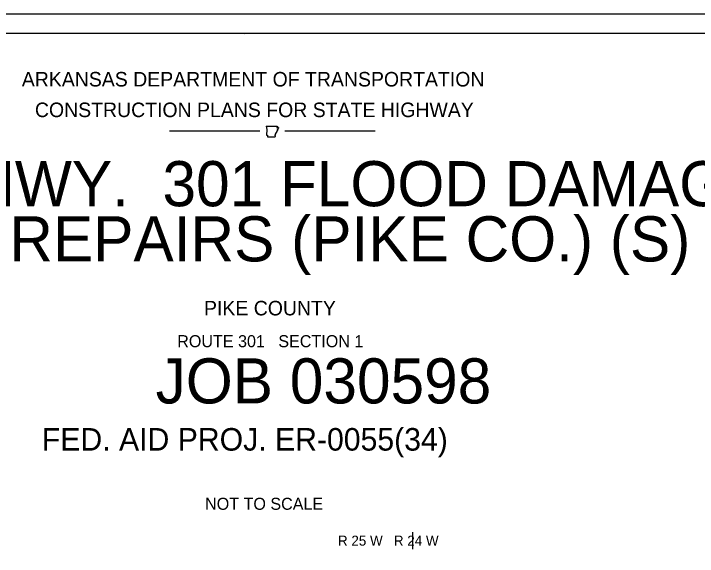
# Model space of a CAD drawing. Extents: x 79818 to 83933, y 50884 to 53307.
# Drawn here: x 81790 to 83152, y 52225 to 53307 of the extents above; entities that cross this region are included whole.
import ezdxf

# ---------------------------------------------------------------- set-up
doc = ezdxf.new("R2010")
doc.units = 0
for name, color, linetype in [('Default', 7, 'Continuous'), ('R_Border', 7, 'Continuous'), ('R_Draft', 7, 'Continuous'), ('R_No Plot', 7, 'Continuous')]:
    doc.layers.add(name, color=color, linetype=linetype)

msp = doc.modelspace()

# ---------------------------------------------------------------- linework, layer by layer
at = {"layer": 'Default'}
for p, q in [((82100.40710546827, 53073.55544833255), (82280.40674546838, 53073.55544833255)), ((82330.40664546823, 53073.55544833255), (82510.40628546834, 53073.55544833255)), ((82585.0374669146, 52239.6791267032), (82585.0374669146, 52273.6791267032))]:
    msp.add_line(p, q, dxfattribs=at)
for points in [[(82293.18594448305, 53083.023599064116), (82299.65393154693, 53083.0195990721), (82305.3299201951, 53083.03159904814), (82312.02590680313, 53083.13559884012), (82315.12990059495, 53083.20759869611)], [(82293.18594448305, 53083.023599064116), (82294.01394282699, 53076.37561236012), (82293.65394354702, 53065.52363406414)], [(82314.16990251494, 53080.08360494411), (82317.20589644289, 53080.23960463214)], [(82295.86593912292, 53064.87963535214), (82295.87393910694, 53061.64364182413), (82310.53390978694, 53061.61964187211)]]:
    msp.add_lwpolyline(points, dxfattribs=at)
for points in [[(82315.12990059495, 53083.20759869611), (82315.14990055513, 53083.03159904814), (82315.20590044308, 53082.93959923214), (82315.2139004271, 53082.77159956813), (82315.28190029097, 53082.699599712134), (82315.39790005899, 53082.62759985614), (82315.50189985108, 53082.51160008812), (82315.52589980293, 53082.37560036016), (82315.49389986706, 53082.23560064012), (82315.48589988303, 53082.07960095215), (82315.46989991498, 53081.94360122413), (82315.4458999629, 53081.81960147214), (82315.34990015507, 53081.719601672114), (82315.25790033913, 53081.64760181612), (82315.17390050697, 53081.56360198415), (82315.1139006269, 53081.4756021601), (82315.00990083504, 53081.37960235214), (82314.90590104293, 53081.27960255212), (82314.82190121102, 53081.19160272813), (82314.7379013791, 53081.07960295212), (82314.69790145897, 53080.95560320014), (82314.60590164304, 53080.86760337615), (82314.53390178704, 53080.78760353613), (82314.43790197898, 53080.679603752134), (82314.38990207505, 53080.57160396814), (82314.29790225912, 53080.4476042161), (82314.27790229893, 53080.32760445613), (82314.2179024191, 53080.231604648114), (82314.21390242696, 53080.215604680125)], [(82317.1618965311, 53080.235604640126), (82317.20589644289, 53080.23960463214), (82317.3418961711, 53080.09560492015), (82317.40189605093, 53079.97560516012), (82317.48989587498, 53079.90760529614), (82317.58989567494, 53079.87160536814), (82317.66589552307, 53079.77960555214), (82317.71789541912, 53079.67960575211), (82317.68989547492, 53079.59160592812), (82317.57789569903, 53079.58360594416), (82317.45389594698, 53079.56360598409), (82317.33389618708, 53079.5676059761), (82317.237896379, 53079.48760613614), (82317.32589620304, 53079.37960635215), (82317.44189597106, 53079.279606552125), (82317.47389590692, 53079.171606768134), (82317.40989603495, 53079.067606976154), (82317.28189629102, 53079.01160708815), (82317.15789653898, 53078.963607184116), (82317.04589676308, 53078.8676073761), (82316.99389686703, 53078.77560756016), (82316.869897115, 53078.73560764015), (82316.74189737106, 53078.69960771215), (82316.62989759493, 53078.68760773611), (82316.50189785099, 53078.663607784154), (82316.37789809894, 53078.60360790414), (82316.3258982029, 53078.4996081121), (82316.34189817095, 53078.35160840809), (82316.33789817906, 53078.195608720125), (82316.46989791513, 53078.14360882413), (82316.5858976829, 53078.13960883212), (82316.69789745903, 53078.0796089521), (82316.68589748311, 53077.99160912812), (82316.60189765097, 53077.879609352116), (82316.50189785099, 53077.791609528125), (82316.40189805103, 53077.747609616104), (82316.30989823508, 53077.663609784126), (82316.34189817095, 53077.579609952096), (82316.4258980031, 53077.52361006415), (82316.48589788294, 53077.431610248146), (82316.47789789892, 53077.34761041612), (82316.38189809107, 53077.2876105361), (82316.27789829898, 53077.31161048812), (82316.2018984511, 53077.411610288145), (82316.11389862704, 53077.44361022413), (82316.03789877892, 53077.47961015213), (82315.9498989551, 53077.427610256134), (82315.9498989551, 53077.31161048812), (82315.917899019, 53077.18761073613), (82315.94589896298, 53077.09561092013), (82315.98189889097, 53076.96761117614), (82315.97789889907, 53076.87161136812), (82315.94589896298, 53076.7356116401), (82315.87789909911, 53076.59561192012), (82315.7978992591, 53076.551612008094), (82315.76589932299, 53076.70361170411), (82315.74989935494, 53076.82761145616), (82315.70189945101, 53076.899611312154), (82315.63789957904, 53076.90361130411), (82315.5538997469, 53076.84361142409), (82315.46189993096, 53076.751611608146), (82315.34590016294, 53076.65161180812), (82315.27790029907, 53076.551612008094), (82315.31390022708, 53076.42761225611), (82315.40190005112, 53076.39561232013), (82315.46989991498, 53076.41961227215), (82315.50589984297, 53076.49961211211), (82315.57389970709, 53076.51161208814), (82315.63789957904, 53076.38761233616)], [(82311.1459085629, 53067.13163084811), (82311.105908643, 53067.03963103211), (82311.06190873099, 53066.87963135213), (82311.07390870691, 53066.7436316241), (82311.13390858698, 53066.62763185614), (82311.22990839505, 53066.563631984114), (82311.33390818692, 53066.47163216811), (82311.32590820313, 53066.331632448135), (82311.26590832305, 53066.27963255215), (82311.12590860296, 53066.315632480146), (82311.01790881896, 53066.36363238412), (82310.92590900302, 53066.335632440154), (82310.80190925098, 53066.27563256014), (82310.70990943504, 53066.263632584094), (82310.71390942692, 53066.07163296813), (82310.83790917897, 53065.93563324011), (82310.94590896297, 53065.93563324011), (82311.06990871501, 53065.91963327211), (82311.11390862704, 53065.77563356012), (82311.04190877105, 53065.65563380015), (82310.92190901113, 53065.59563392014), (82310.76990931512, 53065.66763377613), (82310.66190953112, 53065.74363362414), (82310.55390974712, 53065.81563348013), (82310.41791001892, 53065.85163340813), (82310.34191017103, 53065.83563344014), (82310.30591024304, 53065.66763377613), (82310.36991011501, 53065.51563408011), (82310.4739099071, 53065.41163428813), (82310.56990971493, 53065.27563456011), (82310.55390974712, 53065.17563476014), (82310.48190989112, 53065.14763481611), (82310.35391014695, 53065.11963487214), (82310.27791029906, 53065.079634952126), (82310.25791033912, 53065.04763501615), (82310.297910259, 53064.91163528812), (82310.33391018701, 53064.76363558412), (82310.33391018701, 53064.65163580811), (82310.28991027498, 53064.547636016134), (82310.22191041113, 53064.38763633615), (82310.2299103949, 53064.28363654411), (82310.27791029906, 53064.23563664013), (82310.3379101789, 53064.251636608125), (82310.41791001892, 53064.30763649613), (82310.46990991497, 53064.371636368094), (82310.513909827, 53064.45163620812), (82310.59790965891, 53064.51963607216), (82310.701909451, 53064.45963619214), (82310.72590940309, 53064.3356364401), (82310.66590952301, 53064.227636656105), (82310.5819096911, 53064.17963675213), (82310.477909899, 53064.13963683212), (82310.4019100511, 53064.05163700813), (82310.42191001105, 53063.94763721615), (82310.48190989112, 53063.891637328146), (82310.62990959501, 53063.91963727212), (82310.72990939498, 53063.96363718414), (82310.78590928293, 53064.019637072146), (82310.85390914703, 53064.08763693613), (82310.88990907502, 53064.15563680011), (82310.94190897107, 53064.227636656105), (82311.03390878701, 53064.24763661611), (82311.07790869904, 53064.187636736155), (82311.06190873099, 53064.05163700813), (82311.00590884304, 53063.92363726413), (82310.92990899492, 53063.81563748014), (82310.845909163, 53063.739637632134), (82310.7419093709, 53063.57563796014), (82310.76190933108, 53063.42363826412), (82310.80190925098, 53063.29963851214), (82310.85790913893, 53063.20363870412), (82310.95390894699, 53063.22363866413), (82311.06190873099, 53063.23563864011), (82311.12590860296, 53063.183638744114), (82311.11790861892, 53063.07163896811), (82311.0379087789, 53062.96363918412), (82310.96190893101, 53062.85963939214), (82310.92190901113, 53062.71563968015), (82310.93790897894, 53062.615639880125), (82310.93790897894, 53062.52364006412), (82310.90590904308, 53062.423640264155), (82310.84990915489, 53062.36764037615), (82310.701909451, 53062.3716403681), (82310.5459097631, 53062.3876403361), (82310.46190993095, 53062.33964043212), (82310.477909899, 53062.20364070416), (82310.56990971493, 53062.103640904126), (82310.6339095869, 53062.05164100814), (82310.72590940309, 53061.93964123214), (82310.76590932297, 53061.847641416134), (82310.75390934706, 53061.76764157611), (82310.69790945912, 53061.69964171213), (82310.53390978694, 53061.61964187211)], [(82313.90190305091, 53072.42362026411), (82313.80990323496, 53072.307620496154), (82313.67390350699, 53072.37962035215), (82313.67390350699, 53072.475620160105), (82313.69390346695, 53072.57561996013), (82313.64590356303, 53072.6396198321), (82313.56190373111, 53072.61161988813), (82313.56190373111, 53072.48762013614), (82313.55390374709, 53072.36762037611), (82313.529903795, 53072.19562072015), (82313.58590368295, 53072.1436208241), (82313.71390342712, 53072.12762085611), (82313.80590324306, 53072.10362090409), (82313.86190313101, 53072.011621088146), (82313.85790313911, 53071.89962131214), (82313.8139032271, 53071.79162152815), (82313.74990335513, 53071.7036217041), (82313.64990355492, 53071.67162176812), (82313.56990371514, 53071.72362166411), (82313.53790377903, 53071.82762145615), (82313.50190385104, 53071.91962127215), (82313.43390398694, 53071.98762113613), (82313.36190413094, 53071.91162128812), (82313.34590416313, 53071.77162156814), (82313.34990415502, 53071.651621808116), (82313.34990415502, 53071.48762213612), (82313.45390394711, 53071.37962235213), (82313.51790381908, 53071.25562260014), (82313.49790385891, 53071.14362282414), (82313.42190401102, 53071.011623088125), (82313.38990407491, 53070.8956233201), (82313.35790413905, 53070.73962363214), (82313.36190413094, 53070.567623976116), (82313.33390418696, 53070.39962431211), (82313.27790429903, 53070.2876245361), (82313.17390450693, 53070.195624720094), (82313.10590464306, 53070.13562484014), (82313.04990475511, 53070.075624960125), (82313.02190481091, 53069.95562520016), (82313.00190485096, 53069.87162536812), (82312.92590500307, 53069.77162556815), (82312.86590512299, 53069.76362558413), (82312.81790521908, 53069.80362550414), (82312.80190525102, 53069.87162536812), (82312.80190525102, 53069.9396252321), (82312.76990531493, 53070.00762509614), (82312.66990551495, 53070.03562504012), (82312.58990567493, 53070.031625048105), (82312.55390574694, 53069.9756251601), (82312.605905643, 53069.819625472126), (82312.62590560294, 53069.7196256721), (82312.59790565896, 53069.58362594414), (82312.61390562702, 53069.567625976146), (82312.46990591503, 53069.49162612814), (82312.35390614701, 53069.4796261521), (82312.25790633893, 53069.45162620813), (82312.16590652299, 53069.39162632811), (82312.12190661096, 53069.30362650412), (82312.05790673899, 53069.23162664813), (82312.00190685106, 53069.163626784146), (82311.92590700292, 53069.1316268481), (82311.84190717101, 53069.14762681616), (82311.72990739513, 53069.159626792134), (82311.66590752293, 53069.079626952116), (82311.6859074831, 53068.96362718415), (82311.76190733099, 53068.89562732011), (82311.87390710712, 53068.863627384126), (82311.98990687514, 53068.87162736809), (82312.10190665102, 53068.883627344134), (82312.20590644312, 53068.82762745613), (82312.18590648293, 53068.71962767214), (82312.08590668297, 53068.66762777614), (82311.93790697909, 53068.651627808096), (82311.81790721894, 53068.66362778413), (82311.67390750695, 53068.631627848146), (82311.60190765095, 53068.53962803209), (82311.64190757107, 53068.39962831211), (82311.797907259, 53068.34362842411), (82311.86990711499, 53068.2116286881), (82311.87390710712, 53068.08762893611), (82311.82190721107, 53067.923629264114), (82311.74990735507, 53067.84762941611), (82311.60990763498, 53067.81562948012), (82311.50190785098, 53067.79562952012), (82311.48590788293, 53067.61162988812), (82311.43790797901, 53067.519630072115), (82311.3539081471, 53067.49163012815), (82311.23390838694, 53067.5516300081), (82311.16190853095, 53067.57962995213), (82311.07390870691, 53067.61962987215), (82310.96190893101, 53067.68762973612), (82310.8779090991, 53067.675629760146), (82310.90190905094, 53067.499630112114), (82310.90990903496, 53067.49163012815), (82311.00590884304, 53067.35963039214), (82311.10190865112, 53067.2556306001), (82311.1459085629, 53067.13163084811)], [(82315.63789957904, 53076.38761233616), (82315.6538995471, 53076.27161256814), (82315.585899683, 53076.147612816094), (82315.56189973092, 53076.02361306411), (82315.57389970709, 53075.899613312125), (82315.4458999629, 53075.83161344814), (82315.33390018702, 53075.751613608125), (82315.39790005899, 53075.65561380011), (82315.5178998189, 53075.56761397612), (82315.63789957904, 53075.49961411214), (82315.71389942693, 53075.4316142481), (82315.73389938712, 53075.2676145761), (82315.75389934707, 53075.16361478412), (82315.79389926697, 53075.01961507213), (82315.80989923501, 53074.919615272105), (82315.73789937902, 53074.79961551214), (82315.6538995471, 53074.77561556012), (82315.56589972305, 53074.80361550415), (82315.46189993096, 53074.81161548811), (82315.37790009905, 53074.731615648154), (82315.31790021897, 53074.61961587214), (82315.25790033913, 53074.50761609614), (82315.2139004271, 53074.411616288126), (82315.16990051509, 53074.307616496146), (82315.08190069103, 53074.18761673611), (82314.97390090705, 53074.16761677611), (82314.8459011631, 53074.135616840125), (82314.76990131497, 53074.047617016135), (82314.7819012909, 53073.899617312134), (82314.8539011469, 53073.79961751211), (82314.90990103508, 53073.67561776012), (82314.94990095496, 53073.56761797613), (82314.92990099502, 53073.431618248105), (82314.87390110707, 53073.33161844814), (82314.80190125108, 53073.27161856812), (82314.76990131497, 53073.14361882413), (82314.71790141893, 53073.04761901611), (82314.66990151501, 53073.01561908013), (82314.57390170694, 53073.02361906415), (82314.46990191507, 53073.0436190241), (82314.38190209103, 53073.035619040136), (82314.29790225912, 53072.99161912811), (82314.21390242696, 53073.01961907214), (82314.12590260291, 53073.115618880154), (82314.05390274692, 53073.18761873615), (82313.9739029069, 53073.21561868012), (82313.88990307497, 53073.171618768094), (82313.87390310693, 53073.03961903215), (82313.91390302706, 53072.903619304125), (82313.94990295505, 53072.71961967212), (82313.91390302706, 53072.60761989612), (82313.90190305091, 53072.42362026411)], [(82293.65394354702, 53065.52363406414), (82293.76994331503, 53065.37163436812), (82293.81794321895, 53065.26363458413), (82293.88594308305, 53065.123634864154), (82293.98594288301, 53065.06763497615), (82294.10194265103, 53065.04763501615), (82294.12594260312, 53064.91163528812), (82294.24594236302, 53064.907635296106), (82294.3419421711, 53064.93563524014), (82294.47394190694, 53064.89963531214), (82294.61394162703, 53064.995635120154), (82294.69394146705, 53064.971635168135), (82294.80994123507, 53065.019635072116), (82294.89794105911, 53064.947635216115), (82295.04994075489, 53065.01163508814), (82295.18594048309, 53065.099634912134), (82295.31394022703, 53065.0156350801), (82295.43793997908, 53065.00363510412), (82295.58593968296, 53064.98363514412), (82295.70193945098, 53064.97563516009), (82295.80593924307, 53064.92363526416), (82295.88193909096, 53064.87163536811), (82295.86593912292, 53064.87963535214)]]:
    msp.add_spline(points, degree=3, dxfattribs=at)
at = {"layer": 'R_Border'}
for p, q in [((80723.60034490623, 53268.52016761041), (83885.40034490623, 53268.52016761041)), ((82248.80034490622, 53265.920167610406), (82248.80034490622, 53265.920167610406)), ((82248.80034490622, 53265.920167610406), (82248.80034490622, 53265.920167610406))]:
    msp.add_line(p, q, dxfattribs=at)
at = {"layer": 'R_No Plot'}
msp.add_line((80599.59214731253, 53307.46675708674), (83932.92547931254, 53307.46675708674), dxfattribs=at)
msp.add_lwpolyline([(80599.5254806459, 53307.46675708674), (83932.92547931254, 53307.46675708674), (83932.92547931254, 51174.090758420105), (80599.5254806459, 51174.090758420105)], close=True, dxfattribs=at)

# ---------------------------------------------------------------- texts
at = {"layer": 'Default'}
for s, height, p in [('ARKANSAS DEPARTMENT OF TRANSPORTATION', 28.999736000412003, (81805.91039563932, 53162.260387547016)), ('CONSTRUCTION PLANS FOR STATE HIGHWAY', 28.999736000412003, (81832.04879996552, 53101.20689449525)), ('HWY.  301 FLOOD DAMAGE', 89.99982000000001, (81705.17167546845, 52923.46899963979)), ('REPAIRS (PIKE CO.) (S)', 89.99982000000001, (81780.99829546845, 52813.46921963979)), ('PIKE COUNTY', 28.999940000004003, (82169.08414286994, 52705.83151794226)), ('ROUTE 301   SECTION 1', 23.999952, (82115.67479146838, 52642.441791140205)), ('JOB 030598', 89.99982000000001, (82072.61188546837, 52530.24407328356)), ('NOT TO SCALE', 23.999952, (82171.23373546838, 52318.19959215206)), ('R 25 W   R 24 W', 19.999958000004, (82436.08520692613, 52246.67914770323))]:
    msp.add_text(s, height=height, dxfattribs=at).set_placement(p)
at = {"layer": 'R_Draft'}
msp.add_text('FED. AID PROJ. ER-0055(34)', height=45, dxfattribs=at).set_placement((81845.83976633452, 52436.2292628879))

doc.saveas('drawing.dxf')
